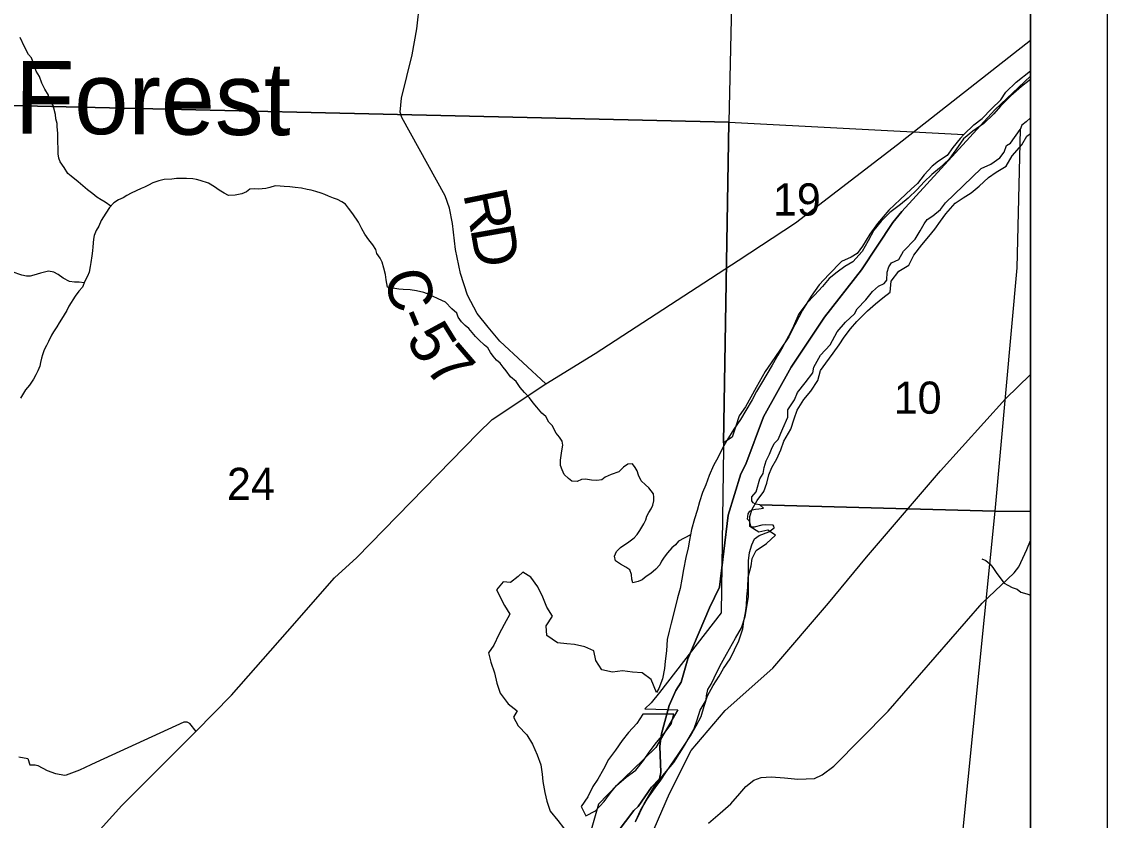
# Model space of a CAD drawing. Extents: x -7.5 to 26.5, y 3.5 to 25.5.
# Drawn here: x 0.131 to 1.543, y 21.108 to 22.147 of the extents above; entities that cross this region are included whole.
import ezdxf

# ---------------------------------------------------------------- set-up
doc = ezdxf.new("R2010")
doc.units = 0
for name, color, linetype in [('GM_X_Corporation', 7, 'Continuous'), ('GM_X_County_Road', 7, 'Continuous'), ('GM_X_County_Road_Text', 7, 'Continuous'), ('GM_X_Major_Lake_Text', 7, 'Continuous'), ('GM_X_Major_River', 7, 'Continuous'), ('GM_X_Minor_River', 7, 'Continuous'), ('GM_X_Rail_Line', 7, 'Continuous'), ('GM_X_Section_Text', 7, 'Continuous'), ('GM_X_State_Route', 7, 'Continuous'), ('SH_Data', 7, 'Continuous')]:
    doc.layers.add(name, color=color, linetype=linetype)

msp = doc.modelspace()

# ---------------------------------------------------------------- linework, layer by layer
at = {"layer": 'GM_X_Corporation'}
for points in [[(1.4431, 17.6), (1.4431, 24.4), (-5.1194, 24.4)], [(0.895, 21.0776), (0.9274, 21.1203), (0.9329, 21.1255), (0.9505, 21.1506), (0.9609, 21.1614), (0.9623, 21.1697), (0.9611, 21.2039), (0.9633, 21.2202), (0.9732, 21.2569), (0.982, 21.2765), (0.9887, 21.2873), (0.9974, 21.3177), (1.0258, 21.3842), (1.0386, 21.4109), (1.0498, 21.5044), (1.0664, 21.5583), (1.0728, 21.571), (1.0961, 21.6327), (1.1319, 21.6971), (1.1754, 21.7621), (1.2233, 21.8239), (1.2641, 21.8855), (1.2758, 21.8996), (1.397, 22.0321), (1.4431, 22.0759), (1.4431, 24.4)], [(1.4431, 18.5934), (1.4431, 22.0759), (1.397, 22.0321), (1.2758, 21.8996), (1.2641, 21.8855), (1.2233, 21.8239), (1.1754, 21.7621), (1.1319, 21.6971), (1.0961, 21.6327), (1.0728, 21.571), (1.0664, 21.5583), (1.0498, 21.5044), (1.0386, 21.4109), (1.0258, 21.3842), (0.9974, 21.3177), (0.9887, 21.2873), (0.982, 21.2765), (0.9732, 21.2569), (0.9633, 21.2202), (0.9611, 21.2039), (0.9623, 21.1697), (0.9609, 21.1614), (0.9505, 21.1506), (0.9329, 21.1255), (0.9274, 21.1203), (0.895, 21.0776)], [(0.9294, 21.1056), (0.9406, 21.1292), (0.9544, 21.152), (0.9673, 21.1684), (0.9794, 21.1829), (0.992, 21.2026), (1.0055, 21.2258), (1.0096, 21.2382), (1.0137, 21.2508), (1.0216, 21.2638), (1.0218, 21.2695), (1.0235, 21.2778), (1.0278, 21.2845), (1.0318, 21.2931), (1.039, 21.3081), (1.0477, 21.3238), (1.0596, 21.3444), (1.0675, 21.3582), (1.072, 21.3728), (1.0764, 21.3985), (1.0764, 21.4451), (1.0778, 21.456), (1.0807, 21.4662), (1.0843, 21.4737), (1.0905, 21.4781), (1.1027, 21.4831), (1.11, 21.4882), (1.1093, 21.4905), (1.1086, 21.4917), (1.0988, 21.4919), (1.0938, 21.4917), (1.0839, 21.4889), (1.0809, 21.4889), (1.0794, 21.4905), (1.0777, 21.497), (1.0751, 21.4993), (1.076, 21.5065), (1.078, 21.5098), (1.0814, 21.5117), (1.0856, 21.5123), (1.0898, 21.513), (1.0959, 21.5136), (1.0914, 21.5182), (1.3966, 21.5097), (1.3056, 20.6048)]]:
    msp.add_lwpolyline(points, dxfattribs=at)
for points in [[(1.0735, 23.0136), (1.0508, 22.0159), (-0.1108, 22.0429), (0.0689, 23.0315)], [(1.4431, 22.0828), (1.4431, 23.0021), (1.0735, 23.0136), (1.0508, 22.0159), (1.3566, 22.0001), (1.3697, 22.0127), (1.3802, 22.0208), (1.3926, 22.0334), (1.4046, 22.0452), (1.4113, 22.0549), (1.4245, 22.0682)], [(-0.1108, 22.0429), (1.0508, 22.0159), (1.0441, 21.5986), (1.044, 21.5921), (1.041, 21.3774), (0.9609, 21.274), (0.95, 21.2606), (0.9418, 21.2525), (0.9845, 21.2515), (0.956, 21.2024), (0.9254, 21.1728), (0.906, 21.154), (0.8815, 21.1284), (0.8624, 21.0618), (-0.2705, 21.1018)], [(1.0508, 22.0159), (1.3566, 22.0001), (1.3519, 21.9949), (1.3421, 21.9831), (1.3347, 21.9726), (1.3235, 21.9653), (1.3154, 21.9587), (1.3049, 21.9476), (1.2963, 21.9364), (1.2878, 21.9287), (1.2738, 21.9154), (1.2591, 21.9013), (1.2443, 21.8843), (1.2344, 21.8701), (1.2246, 21.8548), (1.2179, 21.8451), (1.2099, 21.8404), (1.1972, 21.8347), (1.1809, 21.8176), (1.1684, 21.8043), (1.1579, 21.7894), (1.1468, 21.7715), (1.1369, 21.7524), (1.1289, 21.7367), (1.1171, 21.7192), (1.1058, 21.7028), (1.0983, 21.6916), (1.0864, 21.6706), (1.0725, 21.6456), (1.0643, 21.6337), (1.0598, 21.6205), (1.0553, 21.6059), (1.0441, 21.5986)], [(1.4431, 21.5093), (1.4431, 22.0215), (1.4376, 22.0164), (1.4319, 22.012), (1.4298, 22.0063), (1.4255, 21.8265), (1.3966, 21.5097)], [(1.4298, 22.0063), (1.4255, 21.8265), (1.3966, 21.5097), (1.0914, 21.5182), (1.0854, 21.5191), (1.0824, 21.5207), (1.0806, 21.5234), (1.0807, 21.5283), (1.0865, 21.535), (1.0874, 21.538), (1.0911, 21.552), (1.0955, 21.559), (1.0968, 21.5666), (1.0996, 21.5752), (1.1036, 21.5838), (1.1064, 21.5906), (1.11, 21.5977), (1.1151, 21.6029), (1.1211, 21.6175), (1.1275, 21.6321), (1.1278, 21.6416), (1.1364, 21.6547), (1.1401, 21.6644), (1.1502, 21.6767), (1.16, 21.6897), (1.1613, 21.6972), (1.17, 21.7126), (1.1825, 21.7263), (1.1916, 21.7431), (1.2025, 21.7557), (1.2141, 21.7664), (1.2177, 21.7732), (1.229, 21.7846), (1.2376, 21.7958), (1.2457, 21.8024), (1.253, 21.806), (1.2565, 21.8105), (1.2567, 21.8207), (1.2588, 21.8279), (1.2623, 21.8331), (1.2719, 21.8374), (1.2779, 21.8482), (1.2934, 21.8638), (1.2997, 21.8746), (1.3049, 21.8839), (1.3088, 21.8892), (1.3161, 21.8943), (1.3262, 21.9024), (1.3328, 21.9109), (1.379, 21.9556), (1.3916, 21.9614), (1.4032, 21.9695), (1.409, 21.9769), (1.4119, 21.9855), (1.4173, 21.9888)], [(1.4431, 20.5918), (1.4431, 21.5093), (1.3966, 21.5097), (1.3056, 20.6048)]]:
    msp.add_lwpolyline(points, close=True, dxfattribs=at)
at = {"layer": 'GM_X_County_Road'}
for points in [[(0.8127, 21.6756), (0.7532, 21.7311), (0.7378, 21.7494), (0.7238, 21.7669), (0.7108, 21.7908), (0.7018, 21.8192), (0.6954, 21.8505), (0.6915, 21.8841), (0.6878, 21.904), (0.6818, 21.9201), (0.6255, 22.022), (0.6234, 22.0289), (0.6251, 22.0471), (0.6392, 22.1037), (0.6451, 22.1374), (0.6491, 22.1722)], [(1.0246, 21.1037), (1.0396, 21.1169), (1.0534, 21.1289), (1.0651, 21.1426), (1.0728, 21.1516), (1.0833, 21.16), (1.093, 21.1632), (1.1061, 21.1641), (1.1233, 21.1629), (1.1407, 21.161), (1.1624, 21.1619), (1.1723, 21.1668), (1.1874, 21.1779), (1.2583, 21.2494), (1.3803, 21.3901), (1.4221, 21.4294), (1.428, 21.4374), (1.4384, 21.4599), (1.4431, 21.4716)], [(0.2218, 21.1802), (0.2283, 21.1832), (0.3424, 21.2357), (0.344, 21.2359), (0.3461, 21.2355), (0.3478, 21.2349), (0.3488, 21.2344), (0.3496, 21.2337), (0.3579, 21.223)], [(0.1277, 21.1903), (0.1393, 21.1882), (0.1419, 21.1796), (0.1447, 21.1799), (0.1487, 21.1798), (0.1521, 21.1789), (0.1644, 21.1724), (0.1753, 21.1683), (0.1872, 21.1665), (0.1893, 21.1667), (0.2069, 21.1733), (0.2218, 21.1802)]]:
    msp.add_lwpolyline(points, dxfattribs=at)
at = {"layer": 'GM_X_Major_River'}
msp.add_line((0.9795, 21.2457), (0.939, 21.2455), dxfattribs=at)
for points in [[(1.4431, 22.0717), (1.4413, 22.0704), (1.4317, 22.0626), (1.4177, 22.0504), (1.4041, 22.037), (1.3955, 22.0269), (1.3823, 22.0143), (1.3681, 22.0043), (1.3561, 21.9943), (1.3462, 21.9801), (1.3372, 21.9674), (1.3248, 21.9563), (1.3151, 21.9481), (1.3051, 21.9384), (1.2957, 21.9284), (1.2841, 21.9172)], [(1.3763, 21.9327), (1.3887, 21.9442), (1.3987, 21.9508), (1.4115, 21.9589), (1.4194, 21.9724), (1.4318, 21.9866), (1.4385, 21.9978), (1.4431, 22.0012)], [(1.0148, 21.2427), (1.0189, 21.2562), (1.0233, 21.2694), (1.0305, 21.283), (1.0384, 21.2953), (1.0439, 21.3051), (1.0525, 21.3178), (1.0637, 21.3412), (1.069, 21.3566), (1.0703, 21.3665), (1.0725, 21.3775), (1.0738, 21.3869), (1.0745, 21.3983), (1.0755, 21.4105), (1.0762, 21.4238), (1.08, 21.4389), (1.0813, 21.4484), (1.0865, 21.4585), (1.1, 21.4677), (1.1116, 21.4785), (1.1015, 21.4852), (1.0901, 21.4824), (1.0781, 21.4899), (1.0784, 21.5028), (1.0812, 21.5126), (1.0876, 21.5235), (1.0962, 21.5355), (1.1002, 21.5464), (1.1031, 21.557), (1.1068, 21.5668), (1.1135, 21.5781), (1.1183, 21.5898), (1.1224, 21.6007), (1.1314, 21.6165), (1.1359, 21.63), (1.1396, 21.6414), (1.1486, 21.6552), (1.1576, 21.6661), (1.1667, 21.6799), (1.17, 21.6928), (1.1771, 21.7025), (1.1865, 21.7152), (1.1943, 21.7261), (1.201, 21.7362), (1.2092, 21.747), (1.2174, 21.7567), (1.2314, 21.7705), (1.2415, 21.7798), (1.2511, 21.7876), (1.2608, 21.7949), (1.2622, 21.809), (1.272, 21.8221), (1.2851, 21.8298), (1.2915, 21.8429), (1.3017, 21.8564), (1.311, 21.8672), (1.3189, 21.8769), (1.3263, 21.887), (1.333, 21.8968), (1.3451, 21.9106), (1.3555, 21.9175), (1.3659, 21.9242), (1.3763, 21.9327)], [(1.2841, 21.9172), (1.274, 21.9087), (1.2601, 21.8984), (1.2488, 21.8872), (1.2395, 21.8753), (1.2323, 21.8614), (1.2244, 21.8475), (1.2123, 21.8344), (1.2019, 21.8282), (1.1919, 21.8208), (1.1815, 21.8127), (1.1729, 21.8022), (1.1623, 21.7907), (1.1522, 21.7803), (1.1421, 21.7668), (1.1349, 21.7506), (1.1285, 21.7374), (1.1206, 21.7232), (1.1146, 21.713), (1.1071, 21.6999), (1.0933, 21.6763), (1.087, 21.6654), (1.0814, 21.6548), (1.0731, 21.6406), (1.066, 21.6293), (1.0574, 21.6166), (1.0483, 21.6016), (1.0424, 21.5911), (1.0368, 21.5802), (1.0309, 21.5693), (1.0253, 21.5561), (1.0208, 21.544), (1.0168, 21.5342), (1.0127, 21.5218), (1.0098, 21.5108), (1.0061, 21.4999), (1.0024, 21.4859), (0.9998, 21.4723), (0.9981, 21.462), (0.9948, 21.4496), (0.9921, 21.434), (0.9896, 21.4215), (0.9874, 21.4094), (0.9841, 21.3969), (0.9811, 21.3845), (0.9761, 21.364), (0.9732, 21.3538), (0.9707, 21.3429), (0.97, 21.3281), (0.9682, 21.3148), (0.9672, 21.3053), (0.9646, 21.2917), (0.9598, 21.2792), (0.9569, 21.2738)], [(0.7767, 21.425), (0.7669, 21.417), (0.7575, 21.418), (0.7489, 21.4076), (0.7591, 21.3872), (0.766, 21.3756), (0.7585, 21.3625), (0.7517, 21.3493), (0.7454, 21.3354), (0.7383, 21.3253), (0.7414, 21.3134), (0.7461, 21.2996), (0.7492, 21.2859), (0.7534, 21.2728), (0.7638, 21.2593), (0.7755, 21.2498)], [(0.9569, 21.2738), (0.9498, 21.2909), (0.9382, 21.2995), (0.9257, 21.3002), (0.9128, 21.302), (0.8995, 21.3004), (0.8859, 21.3033), (0.8778, 21.3157), (0.8754, 21.3283), (0.8634, 21.3335), (0.8502, 21.3365), (0.8403, 21.3371), (0.8282, 21.3385), (0.8144, 21.3479), (0.8135, 21.3605), (0.8214, 21.3732), (0.8144, 21.3848), (0.809, 21.3978), (0.8025, 21.4113), (0.7933, 21.424), (0.7828, 21.4304), (0.7767, 21.425)], [(0.7755, 21.2498), (0.7709, 21.2419), (0.777, 21.2304), (0.7881, 21.219), (0.7957, 21.2066), (0.8017, 21.1927), (0.8066, 21.1797), (0.8081, 21.1674), (0.8089, 21.1579), (0.8115, 21.1438), (0.8142, 21.1323), (0.8184, 21.1196), (0.8286, 21.1075), (0.8432, 21.0881)], [(0.939, 21.2455), (0.9314, 21.2336), (0.9204, 21.2218), (0.9121, 21.2114), (0.9034, 21.1988), (0.8946, 21.1865), (0.8878, 21.1742), (0.8805, 21.1611), (0.8742, 21.1514), (0.8673, 21.1383), (0.8589, 21.1257), (0.865, 21.1133)], [(0.865, 21.1133), (0.8773, 21.1201), (0.8886, 21.1319), (0.897, 21.1434), (0.9049, 21.153), (0.9174, 21.1637), (0.9298, 21.1728), (0.9397, 21.1854), (0.9472, 21.1962), (0.9567, 21.2088), (0.9662, 21.2203), (0.9757, 21.2326), (0.9795, 21.2457)], [(0.93, 21.1067), (0.9358, 21.1205), (0.9446, 21.1351), (0.9549, 21.15), (0.9624, 21.16), (0.9688, 21.1697), (0.9756, 21.1794), (0.9843, 21.192), (0.9927, 21.205), (1.0011, 21.2177), (1.0083, 21.2304), (1.0148, 21.2427)]]:
    msp.add_lwpolyline(points, dxfattribs=at)
at = {"layer": 'GM_X_Minor_River'}
for points in [[(0.2472, 21.9069), (0.2396, 21.9117), (0.2344, 21.9148), (0.2291, 21.9184), (0.2238, 21.9226), (0.2167, 21.9281), (0.2047, 21.9382), (0.1957, 21.9459), (0.1912, 21.9494), (0.1864, 21.9571), (0.1812, 21.9645), (0.1794, 21.9691), (0.1787, 21.9748), (0.1785, 21.9805), (0.1783, 21.9916), (0.1784, 21.9969), (0.1781, 22.0018), (0.1775, 22.0099), (0.1772, 22.0144), (0.1758, 22.0205), (0.1751, 22.0259), (0.1723, 22.0377), (0.1675, 22.0454), (0.166, 22.0512), (0.1612, 22.0589), (0.1576, 22.0669), (0.1543, 22.0754), (0.1499, 22.0823), (0.1473, 22.09), (0.1441, 22.0995), (0.14, 22.1042), (0.1348, 22.1142), (0.1293, 22.1261)], [(0.6217, 21.7988), (0.6167, 21.7997), (0.6114, 21.8002), (0.6069, 21.8014), (0.6051, 21.8109), (0.6045, 21.8178), (0.6024, 21.8258), (0.5999, 21.8339), (0.5973, 21.8389), (0.5932, 21.845), (0.5918, 21.8504), (0.5877, 21.8562), (0.5829, 21.8627), (0.5777, 21.8704), (0.5736, 21.8773), (0.5692, 21.8858), (0.5618, 21.8966), (0.5562, 21.9039), (0.5525, 21.9093), (0.5476, 21.9124), (0.542, 21.9152), (0.5367, 21.9172), (0.5302, 21.9199), (0.5253, 21.9219), (0.5208, 21.9235), (0.5136, 21.9259), (0.5075, 21.9275), (0.5026, 21.9284), (0.495, 21.93), (0.4867, 21.9309), (0.4798, 21.9318), (0.4726, 21.9323), (0.4673, 21.9328), (0.4608, 21.9333), (0.4539, 21.9311), (0.4486, 21.9296), (0.439, 21.929), (0.4337, 21.9291), (0.428, 21.9288), (0.4234, 21.9255), (0.4176, 21.9229), (0.4088, 21.9208), (0.4004, 21.9205), (0.3944, 21.9237), (0.388, 21.9276), (0.382, 21.9319), (0.3741, 21.9366), (0.3635, 21.9402), (0.3586, 21.9414), (0.3536, 21.9422), (0.3456, 21.9427), (0.3377, 21.9429), (0.3327, 21.9426), (0.3266, 21.9419), (0.3167, 21.9413), (0.3098, 21.9395), (0.3018, 21.937), (0.296, 21.934), (0.291, 21.9314), (0.2864, 21.9296), (0.2803, 21.9267), (0.2737, 21.9237), (0.268, 21.9204), (0.2633, 21.9174), (0.2572, 21.9148), (0.251, 21.9111), (0.2456, 21.9051), (0.2405, 21.8976), (0.2346, 21.8882), (0.2315, 21.8806), (0.2283, 21.8749), (0.2255, 21.8685), (0.2247, 21.8636), (0.2237, 21.8537), (0.2232, 21.8484), (0.2224, 21.8419), (0.2211, 21.8332), (0.2202, 21.8282), (0.2189, 21.821), (0.2169, 21.8157), (0.2134, 21.8089), (0.2102, 21.8013), (0.2055, 21.7961), (0.2009, 21.7897), (0.1926, 21.7765), (0.1899, 21.7708), (0.1863, 21.7651), (0.1832, 21.7595), (0.1801, 21.755), (0.1769, 21.7497), (0.1726, 21.7433), (0.1702, 21.7387), (0.1663, 21.7304), (0.1635, 21.7255), (0.1604, 21.7199), (0.1584, 21.7134), (0.1568, 21.7089), (0.1559, 21.7032), (0.1547, 21.6986), (0.1523, 21.6926), (0.1495, 21.6873)], [(0.2125, 21.8068), (0.2058, 21.8079), (0.2001, 21.808), (0.1932, 21.8088), (0.1853, 21.8132), (0.1785, 21.8178), (0.1729, 21.821), (0.166, 21.8219), (0.1557, 21.8197), (0.1469, 21.8168), (0.1423, 21.8154), (0.1374, 21.8155), (0.1313, 21.8167), (0.1188, 21.8211)], [(1.0011, 21.4792), (0.9853, 21.4707), (0.9814, 21.4662), (0.9768, 21.4621), (0.971, 21.4557), (0.9667, 21.45), (0.9635, 21.4447), (0.9612, 21.4402), (0.9561, 21.4342), (0.9495, 21.4286), (0.9434, 21.4249), (0.9383, 21.4204), (0.933, 21.4182), (0.9261, 21.4164), (0.9247, 21.4214), (0.9244, 21.4275), (0.9222, 21.4336), (0.917, 21.4371), (0.9102, 21.4407), (0.9034, 21.445), (0.902, 21.4511), (0.9048, 21.4575), (0.9102, 21.4624), (0.921, 21.4698), (0.9279, 21.475), (0.9318, 21.4795), (0.9353, 21.4848), (0.9404, 21.4935), (0.9428, 21.4984), (0.9444, 21.5033), (0.9468, 21.5083), (0.9499, 21.5128), (0.9519, 21.5177), (0.9532, 21.5234), (0.9533, 21.528), (0.953, 21.5325), (0.947, 21.5402), (0.9425, 21.5441), (0.9369, 21.5492), (0.9336, 21.5568), (0.9318, 21.5622), (0.9292, 21.5668), (0.9255, 21.5715), (0.9194, 21.5708), (0.914, 21.5671), (0.9078, 21.5611), (0.8978, 21.5574), (0.8902, 21.5541), (0.8855, 21.5508), (0.879, 21.5497), (0.8722, 21.5502), (0.8646, 21.5515), (0.8593, 21.5512), (0.8535, 21.5486), (0.8467, 21.5487), (0.8422, 21.5522), (0.8369, 21.5576), (0.834, 21.5638), (0.8318, 21.5692), (0.8319, 21.576), (0.8337, 21.5882), (0.835, 21.5958), (0.8343, 21.6011), (0.8306, 21.6061), (0.8265, 21.6115), (0.821, 21.6211), (0.8169, 21.6258), (0.8128, 21.6331), (0.8075, 21.6374), (0.8012, 21.6451), (0.7964, 21.6509), (0.7915, 21.6574), (0.7852, 21.6644), (0.7796, 21.6706), (0.7744, 21.6787), (0.7669, 21.6845), (0.7614, 21.6926), (0.7572, 21.6972), (0.7535, 21.7022), (0.7487, 21.7065), (0.7446, 21.7115), (0.7408, 21.7162), (0.7375, 21.7223), (0.733, 21.7258), (0.7259, 21.7328), (0.7214, 21.737), (0.7129, 21.7475), (0.708, 21.7513), (0.7031, 21.756), (0.699, 21.7622), (0.6972, 21.7675), (0.6905, 21.773), (0.6823, 21.7819), (0.6728, 21.7862), (0.6657, 21.7897), (0.6611, 21.7917), (0.6543, 21.7945), (0.6449, 21.7966), (0.6365, 21.7978), (0.6274, 21.7984), (0.6217, 21.7988)], [(0.1495, 21.6873), (0.1464, 21.6816), (0.1416, 21.6737), (0.1362, 21.6677), (0.1295, 21.6567)], [(1.38, 21.4479), (1.3853, 21.4456), (1.3902, 21.4413), (1.3943, 21.4367), (1.3984, 21.4301), (1.4047, 21.4216), (1.4088, 21.4162), (1.4137, 21.4135), (1.4193, 21.4107), (1.4258, 21.4084), (1.4306, 21.4045), (1.4352, 21.4033), (1.4397, 21.4017), (1.4431, 21.4004)]]:
    msp.add_lwpolyline(points, dxfattribs=at)
at = {"layer": 'GM_X_Rail_Line'}
msp.add_lwpolyline([(1.4431, 19.1101), (1.4357, 19.1342), (1.3427, 19.5285), (1.324, 19.582), (1.3131, 19.6257), (1.2952, 19.6968), (1.2713, 19.7553), (1.113, 20.0785), (0.874, 20.5379), (0.8376, 20.6155), (0.8218, 20.6694), (0.8218, 20.7344), (0.8281, 20.8009), (0.86, 20.8897), (0.9437, 21.0734), (0.9739, 21.1424), (1.0019, 21.1983), (1.046, 21.2506), (1.108, 21.3057), (1.1804, 21.39), (1.23, 21.4499), (1.3263, 21.5623), (1.4109, 21.6558), (1.4431, 21.6878)], dxfattribs=at)
at = {"layer": 'GM_X_State_Route'}
for points in [[(0.3579, 21.223), (0.4041, 21.2703), (0.477, 21.3532), (0.5379, 21.423), (0.5673, 21.4497), (0.7247, 21.6112), (0.7433, 21.629), (0.8127, 21.6756), (0.8771, 21.7151), (1.063, 21.8362), (1.1374, 21.8848), (1.2701, 21.987), (1.4431, 22.1228)], [(0.5968, 19.872), (0.5838, 19.8956), (0.4889, 20.0716), (0.4301, 20.1759), (0.3986, 20.2327), (0.3896, 20.2492), (0.366, 20.2973), (0.3375, 20.3583), (0.2705, 20.5707), (0.2027, 20.7838), (0.1701, 20.8958), (0.1663, 20.9449), (0.1735, 20.9929), (0.1881, 21.0328), (0.2176, 21.0781), (0.2213, 21.0822), (0.2613, 21.1268), (0.3579, 21.223)]]:
    msp.add_lwpolyline(points, dxfattribs=at)
at = {"layer": 'SH_Data'}
for p, q in [((1.5431, 24.5), (1.5431, 17.5)), ((1.4431, 24.4), (1.4431, 17.6))]:
    msp.add_line(p, q, dxfattribs=at)

# ---------------------------------------------------------------- texts
at = {"layer": 'GM_X_County_Road_Text'}
for s, rotation, p in [('R', 281.5696, (0.7052, 21.9228)), ('D', 280.0058, (0.7145, 21.8775)), ('C', 283.6065, (0.6022, 21.8183)), ('-', 292.7159, (0.6163, 21.7635)), ('5', 301.7465, (0.6298, 21.7333)), ('7', 310.7166, (0.6539, 21.6957))]:
    msp.add_text(s, height=0.0568, rotation=rotation, dxfattribs=at).set_placement(p)
at = {"layer": 'GM_X_Major_Lake_Text'}
msp.add_text('Forest', height=0.09469, rotation=359.6558, dxfattribs=at).set_placement((0.122, 22.0011))
at = {"layer": 'GM_X_Section_Text'}
for s, p in [('19', (1.1082, 21.8945)), ('10', (1.2653, 21.6366)), ('24', (0.3982, 21.5244))]:
    msp.add_text(s, height=0.04186, rotation=0, dxfattribs=at).set_placement(p)

doc.saveas('drawing.dxf')
